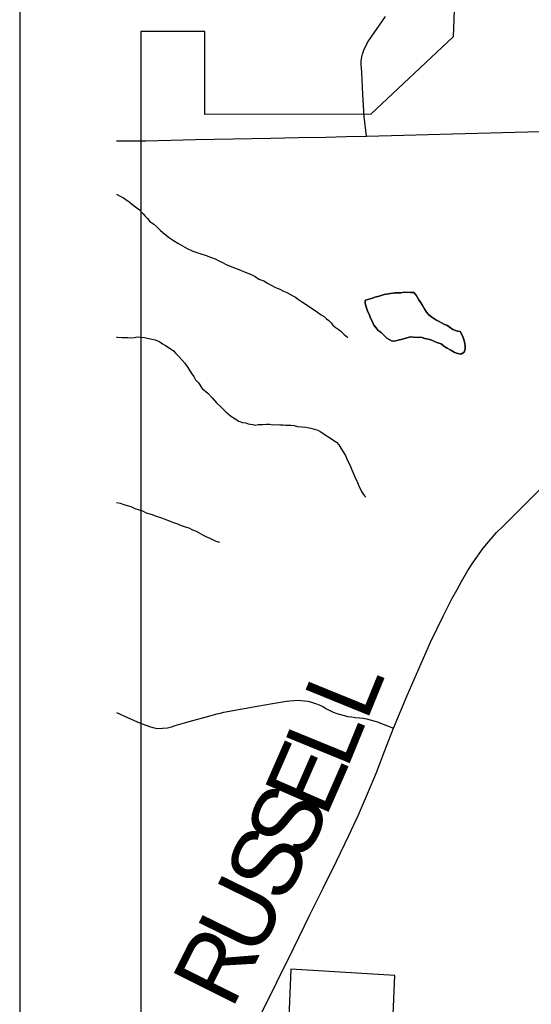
# Model space of a CAD drawing. Extents: x -11.4 to 84.1, y 11.1 to 59.
# Drawn here: x 26.165 to 26.589, y 42.977 to 43.792 of the extents above; entities that cross this region are included whole.
import ezdxf

# ---------------------------------------------------------------- set-up
doc = ezdxf.new("R2010")
doc.units = 0
for name, color, linetype in [('GM_X_Corporation', 7, 'Continuous'), ('GM_X_County_Road', 7, 'Continuous'), ('GM_X_County_Road_Text', 7, 'Continuous'), ('GM_X_Minor_Lake', 7, 'Continuous'), ('GM_X_Minor_River', 7, 'Continuous'), ('GM_X_State_Route', 7, 'Continuous'), ('GM_X_Township_Road', 7, 'Continuous'), ('SH_Data', 7, 'Continuous')]:
    doc.layers.add(name, color=color, linetype=linetype)

msp = doc.modelspace()

# ---------------------------------------------------------------- linework, layer by layer
at = {"layer": 'GM_X_Corporation'}
msp.add_line((26.26551, 43.78252), (26.26551, 42.05419), dxfattribs=at)
for points in [[(26.26551, 44.1125), (26.35403, 44.13774), (26.35174, 44.02891), (26.3915, 44.02807), (26.39254, 44.07752), (26.42, 44.07694), (26.42053, 44.10212), (26.43374, 44.10153), (26.43322, 44.07666), (26.45215, 44.07626), (26.45284, 44.10868), (26.48152, 44.10657), (26.53728, 44.10166), (26.53027, 43.96408), (26.5283, 43.89599), (26.52402, 43.77817), (26.45588, 43.71398), (26.3185, 43.71396), (26.31849, 43.78253), (26.26551, 43.78252)], [(26.25991, 42.77689), (26.3573, 42.77098), (26.46771, 42.772), (26.47367, 42.91013), (26.47177, 42.91025), (26.47569, 43.00088), (26.38967, 43.0061), (26.38652, 42.93306), (26.41492, 42.93233), (26.41435, 42.91909), (26.38576, 42.91982), (26.3836, 42.86986), (26.25991, 42.87737)]]:
    msp.add_lwpolyline(points, dxfattribs=at)
at = {"layer": 'GM_X_County_Road'}
msp.add_lwpolyline([(26.36418, 42.96745), (26.37794, 42.99531), (26.39169, 43.02317), (26.40544, 43.05102), (26.41647, 43.07335), (26.42749, 43.09568), (26.43764, 43.11675), (26.44551, 43.13399), (26.4531, 43.15136), (26.46035, 43.16887), (26.46744, 43.18735), (26.47453, 43.20583), (26.48588, 43.23284), (26.49547, 43.25486), (26.50507, 43.27687), (26.51555, 43.29843), (26.51915, 43.30571), (26.5229, 43.31292), (26.52679, 43.32006), (26.53077, 43.32714), (26.53612, 43.33623), (26.54006, 43.34266), (26.54868, 43.35462), (26.55978, 43.36764), (26.5654, 43.37327), (26.58288, 43.39074), (26.59671, 43.40457)], dxfattribs=at)
at = {"layer": 'GM_X_Minor_Lake'}
for points in [[(26.5301, 43.51538), (26.53311, 43.51697), (26.53381, 43.51965), (26.53375, 43.52231), (26.5333, 43.52573), (26.53208, 43.52913), (26.53128, 43.53102), (26.52968, 43.53403), (26.52739, 43.53437), (26.52355, 43.53581), (26.52046, 43.53803), (26.51852, 43.53952), (26.51661, 43.53986), (26.51429, 43.54134), (26.51236, 43.54244), (26.50966, 43.54391), (26.50618, 43.54612), (26.50386, 43.54798), (26.50191, 43.55022), (26.50033, 43.55248), (26.49835, 43.55624), (26.49677, 43.55849), (26.49559, 43.56038), (26.49322, 43.56413), (26.49127, 43.56638), (26.4886, 43.56632), (26.48365, 43.5666), (26.48061, 43.56616), (26.47566, 43.56606), (26.46693, 43.56474), (26.46277, 43.56351), (26.45898, 43.56268), (26.45709, 43.56188), (26.45138, 43.56008), (26.45105, 43.55947)], [(26.45105, 43.55947), (26.45138, 43.56008), (26.45709, 43.56188), (26.45898, 43.56268), (26.46277, 43.56351), (26.46693, 43.56474), (26.47566, 43.56606), (26.48061, 43.56616), (26.48365, 43.5666), (26.4886, 43.56632), (26.49127, 43.56638), (26.49322, 43.56413), (26.49559, 43.56038), (26.49677, 43.55849), (26.49835, 43.55624), (26.50033, 43.55248), (26.50191, 43.55022), (26.50386, 43.54798), (26.50618, 43.54612), (26.50966, 43.54391), (26.51236, 43.54244), (26.51429, 43.54134), (26.51661, 43.53986), (26.51852, 43.53952), (26.52046, 43.53803), (26.52355, 43.53581), (26.52739, 43.53437), (26.52968, 43.53403), (26.53128, 43.53102), (26.53208, 43.52913), (26.5333, 43.52573), (26.53375, 43.52231), (26.53381, 43.51965), (26.53311, 43.51697), (26.5301, 43.51538), (26.52665, 43.51608), (26.52473, 43.51718), (26.52203, 43.51865), (26.51894, 43.52049), (26.51624, 43.52196), (26.51392, 43.52381), (26.51123, 43.5249), (26.50854, 43.52599), (26.50623, 43.52708), (26.50316, 43.52778), (26.50048, 43.52849), (26.49818, 43.5292), (26.49589, 43.52954), (26.49399, 43.52912), (26.49094, 43.52944), (26.48865, 43.52977), (26.48562, 43.52895), (26.48184, 43.52773), (26.47843, 43.5269), (26.47653, 43.52648), (26.4735, 43.52604), (26.46887, 43.52861), (26.46692, 43.53085), (26.46419, 43.53346), (26.46187, 43.53494), (26.45991, 43.53756), (26.45835, 43.53944), (26.45715, 43.54208), (26.45556, 43.54509), (26.45474, 43.54774), (26.45314, 43.55114), (26.45233, 43.55302), (26.45152, 43.55529), (26.45108, 43.55795), (26.45105, 43.55947)], [(26.45105, 43.55947), (26.45108, 43.55795), (26.45152, 43.55529), (26.45233, 43.55302), (26.45314, 43.55114), (26.45474, 43.54774), (26.45556, 43.54509), (26.45715, 43.54208), (26.45835, 43.53944), (26.45991, 43.53756), (26.46187, 43.53494), (26.46419, 43.53346), (26.46692, 43.53085), (26.46887, 43.52861), (26.4735, 43.52604), (26.47653, 43.52648), (26.47843, 43.5269), (26.48184, 43.52773), (26.48562, 43.52895), (26.48865, 43.52977), (26.49094, 43.52944), (26.49399, 43.52912), (26.49589, 43.52954), (26.49818, 43.5292), (26.50048, 43.52849), (26.50316, 43.52778), (26.50623, 43.52708), (26.50854, 43.52599), (26.51123, 43.5249), (26.51392, 43.52381), (26.51624, 43.52196), (26.51894, 43.52049), (26.52203, 43.51865), (26.52473, 43.51718), (26.52665, 43.51608), (26.5301, 43.51538)]]:
    msp.add_lwpolyline(points, dxfattribs=at)
at = {"layer": 'GM_X_Minor_River'}
for points in [[(26.2454, 43.6479), (26.24881, 43.64598), (26.25112, 43.64488), (26.25306, 43.6434), (26.25576, 43.64155), (26.25887, 43.63895), (26.26118, 43.63747), (26.26429, 43.63487), (26.26741, 43.63151), (26.26897, 43.62964), (26.27092, 43.62777), (26.27288, 43.62515), (26.27636, 43.62293), (26.27869, 43.6207), (26.28181, 43.61771), (26.2853, 43.61474), (26.28918, 43.61177), (26.29265, 43.60956), (26.29613, 43.60734), (26.29999, 43.60514), (26.30384, 43.60293), (26.30846, 43.60074), (26.31345, 43.59894), (26.31958, 43.59716), (26.32304, 43.5957), (26.32689, 43.59426), (26.32997, 43.5928), (26.33304, 43.59134), (26.33613, 43.5895), (26.34074, 43.58769), (26.3465, 43.58552), (26.35188, 43.58334), (26.35611, 43.58153), (26.35996, 43.5797), (26.36306, 43.57748), (26.36728, 43.57604), (26.37036, 43.5742), (26.37383, 43.57237), (26.37692, 43.57053)], [(26.37692, 43.57053), (26.38038, 43.56908), (26.38346, 43.56761), (26.38615, 43.56653), (26.38885, 43.56506), (26.39117, 43.56358), (26.39347, 43.56249), (26.3958, 43.56063), (26.39928, 43.55842), (26.40817, 43.55251), (26.41164, 43.55029), (26.41474, 43.54807), (26.41706, 43.54659), (26.419, 43.54473), (26.42094, 43.54325), (26.42289, 43.54138), (26.42445, 43.53951), (26.4264, 43.53764), (26.42872, 43.53617), (26.43065, 43.53469), (26.43376, 43.5317), (26.43648, 43.52947), (26.43686, 43.52948)], [(26.2454, 43.52951), (26.24606, 43.52941), (26.24987, 43.52911), (26.25178, 43.52915), (26.25482, 43.52921), (26.25711, 43.52887), (26.26015, 43.52932), (26.26243, 43.52974), (26.26586, 43.52943), (26.26853, 43.52911), (26.27083, 43.52877), (26.27733, 43.52738), (26.28118, 43.52556), (26.2835, 43.52408), (26.28582, 43.5226), (26.2889, 43.52076), (26.29239, 43.51817), (26.29434, 43.51592), (26.29707, 43.51331), (26.29941, 43.5107), (26.30175, 43.50808), (26.30372, 43.50507), (26.30569, 43.50207), (26.30728, 43.49943), (26.30924, 43.49681), (26.31082, 43.49417), (26.31316, 43.49156), (26.31631, 43.48705), (26.32097, 43.48296), (26.32448, 43.47922), (26.328, 43.4751), (26.33189, 43.47138), (26.33578, 43.46765), (26.33966, 43.4643), (26.34353, 43.46171), (26.34662, 43.45987), (26.34969, 43.45879), (26.35236, 43.45847), (26.35428, 43.45774), (26.35811, 43.45706), (26.36002, 43.45672), (26.36267, 43.45715), (26.36458, 43.45719), (26.36648, 43.45723), (26.36915, 43.45729), (26.37181, 43.45734), (26.37448, 43.45701), (26.37829, 43.45709), (26.38058, 43.45676), (26.38325, 43.45681), (26.38516, 43.45647), (26.38744, 43.45651), (26.38972, 43.45656), (26.3924, 43.45624), (26.39508, 43.45553), (26.39852, 43.45522), (26.40195, 43.45491), (26.40615, 43.45423), (26.41191, 43.45244), (26.41383, 43.45134), (26.41615, 43.44986), (26.41886, 43.44802), (26.42233, 43.4458)], [(26.42233, 43.4458), (26.42504, 43.44395), (26.42736, 43.44248), (26.42931, 43.44023), (26.4309, 43.4376), (26.43287, 43.43459), (26.43484, 43.43159), (26.43645, 43.42743), (26.43844, 43.42366), (26.44006, 43.41951), (26.44166, 43.41573), (26.44286, 43.41309), (26.44406, 43.41045), (26.44527, 43.40781), (26.44608, 43.40554), (26.44726, 43.40366), (26.44807, 43.40177), (26.44925, 43.3999), (26.45043, 43.39802), (26.4516, 43.3969)], [(26.2454, 43.39268), (26.24834, 43.392), (26.25141, 43.39092), (26.25409, 43.39022), (26.25716, 43.38914), (26.26062, 43.38769), (26.26407, 43.38661), (26.26676, 43.38553), (26.26984, 43.38406), (26.27483, 43.38264), (26.27828, 43.38119), (26.28173, 43.38012), (26.28481, 43.37904), (26.2875, 43.37795), (26.2898, 43.37724), (26.29211, 43.37614), (26.29518, 43.37506), (26.29749, 43.37397), (26.29979, 43.37325), (26.30209, 43.37254), (26.30516, 43.37146), (26.30824, 43.37), (26.31131, 43.36892), (26.31324, 43.36781), (26.31709, 43.36561), (26.3194, 43.36451), (26.32248, 43.36305), (26.32479, 43.36195), (26.32749, 43.36049), (26.33055, 43.35979)]]:
    msp.add_lwpolyline(points, dxfattribs=at)
at = {"layer": 'GM_X_State_Route'}
msp.add_lwpolyline([(26.2454, 43.69214), (26.24927, 43.69212), (26.26974, 43.69197), (26.29028, 43.69256), (26.31081, 43.69315), (26.34187, 43.69374), (26.37293, 43.69433), (26.39577, 43.69476), (26.4186, 43.6952), (26.43533, 43.6956), (26.45207, 43.69601), (26.48313, 43.6968), (26.5033, 43.69732), (26.52347, 43.69783), (26.55452, 43.69863), (26.58558, 43.69942), (26.61664, 43.70021)], dxfattribs=at)
at = {"layer": 'GM_X_Township_Road'}
for points in [[(26.45207, 43.69601), (26.45038, 43.71221), (26.44929, 43.73046), (26.44819, 43.74871), (26.44787, 43.75528), (26.44779, 43.75809), (26.44834, 43.76158), (26.4488, 43.76368), (26.44997, 43.76703), (26.45308, 43.77356), (26.45712, 43.77948), (26.46055, 43.78422), (26.46802, 43.79506)], [(26.2454, 43.21875), (26.25493, 43.21435), (26.26449, 43.21011), (26.27256, 43.20721), (26.27549, 43.2064), (26.27929, 43.20553), (26.28763, 43.20604), (26.29078, 43.20692), (26.294, 43.20787), (26.30156, 43.21026), (26.30862, 43.21209), (26.32071, 43.21547), (26.32877, 43.21749), (26.33133, 43.21818), (26.33422, 43.21892), (26.36164, 43.22387), (26.37437, 43.22616), (26.38609, 43.22801), (26.38881, 43.22827), (26.39218, 43.22854), (26.3951, 43.22879), (26.40126, 43.22847), (26.40363, 43.22815), (26.4068, 43.22733), (26.40998, 43.22627), (26.41301, 43.22502), (26.41599, 43.22354), (26.41903, 43.22182), (26.42182, 43.22038), (26.42466, 43.21909), (26.4276, 43.21797), (26.43058, 43.21698), (26.43362, 43.21616), (26.4367, 43.2155), (26.43977, 43.215), (26.4429, 43.21465), (26.44631, 43.21438), (26.44934, 43.21398), (26.45228, 43.21343), (26.45527, 43.21272), (26.45815, 43.21185), (26.461, 43.21085), (26.47453, 43.20583)]]:
    msp.add_lwpolyline(points, dxfattribs=at)
at = {"layer": 'SH_Data'}
msp.add_line((26.16529, 47.54828), (26.16529, 40.54828), dxfattribs=at)

# ---------------------------------------------------------------- texts
at = {"layer": 'GM_X_County_Road_Text'}
for s, rotation, p in [('L', 67.84503, (26.4521, 43.21042)), ('L', 67.72327, (26.43594, 43.17097)), ('E', 66.37196, (26.41833, 43.13069)), ('S', 64.61866, (26.40112, 43.09432)), ('S', 63.92403, (26.38394, 43.05922)), ('U', 63.90795, (26.36194, 43.0143)), ('R', 63.40003, (26.3408, 42.97208))]:
    msp.add_text(s, height=0.05682, rotation=rotation, dxfattribs=at).set_placement(p)

doc.saveas('drawing.dxf')
